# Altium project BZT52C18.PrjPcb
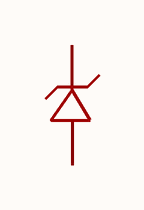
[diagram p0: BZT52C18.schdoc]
1 sheet, 1 parts. Net scope: global (net labels, ports and power ports of the same name join across sheets).

## Sheet BZT52C18.schdoc
size 127 x 101 mm

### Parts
D?  bzt52c18_c43490  [SOD-123_L2.8-W1.8-LS3.7-RD]  (value not drawn)

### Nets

Not connected (* = marked no-connect by the designer): D? 1(C) 2(A)

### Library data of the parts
D? = bzt52c18_c43490: 二极管配置:1个独立式;稳压值(标称值):18V;稳压值(范围值):16.8V~19.1V;耗散功率(Pd):500mW;; Manufacturer: CJ(江苏长电/长晶); AddInBom: yes; ModelId: 7884390a25fb4c08947731ebfba7e3f8; ModelTransform: 144.8816,62.992,0,0,0,0,0,0,0; Diode Configuration: 1个独立式; Zener Voltage(Nom): 18V; Reverse Leakage Current (Ir): 100nA@12.6V; Pd - Power Dissipation: 500mW; Impedance(Zzt): 45Ω; Impedance(Zzk): 225Ω; Operating Junction Temperature Range: -55℃~+150℃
